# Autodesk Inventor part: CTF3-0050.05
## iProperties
Shininess: 64.0
Length Units: 11269
Angle Units: 11279
Time Units: 11290
Mass Units: 11283
Length Display Precision: 3
Angle Display Precision: 2
Compacted: True
Part Number: CTF3-0050.05
Document SubType Name: Modeling
Created: 2003-11
Designer: Lollo
Density: 0.0
Volumn: 0.0
Area: 0.0
PropertySet Name: Model Information
Control State: 0
Master: False
Checked Out: False
Author: Lollo
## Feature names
1. Estrusione1 [Extrusion]
2. Foro5 [Hole]
